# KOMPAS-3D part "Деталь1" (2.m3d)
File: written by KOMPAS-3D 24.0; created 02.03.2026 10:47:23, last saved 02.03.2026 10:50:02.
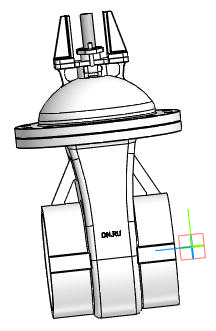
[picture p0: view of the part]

Document properties: Автор: R2D2; Полное имя файла: E:\Работа\Зайцев\GVWR2121M-2W-F-ОСТ Задвижка клиновая с видвижным штоком Ду50-300 Ру16\DN300\Исходные материалы\2.m3d

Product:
- Body: Твердое тело1  | qty 1
    Масса: 135.375105
- Part/product: Деталь1
    Масса: 135.375105
    additional columns: Типовые

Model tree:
1. Твердое тело1  (labels: Твердое тело1)
2. Эскиз:1
3. Элемент выдавливания:2
     Расстояние 1 = 500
